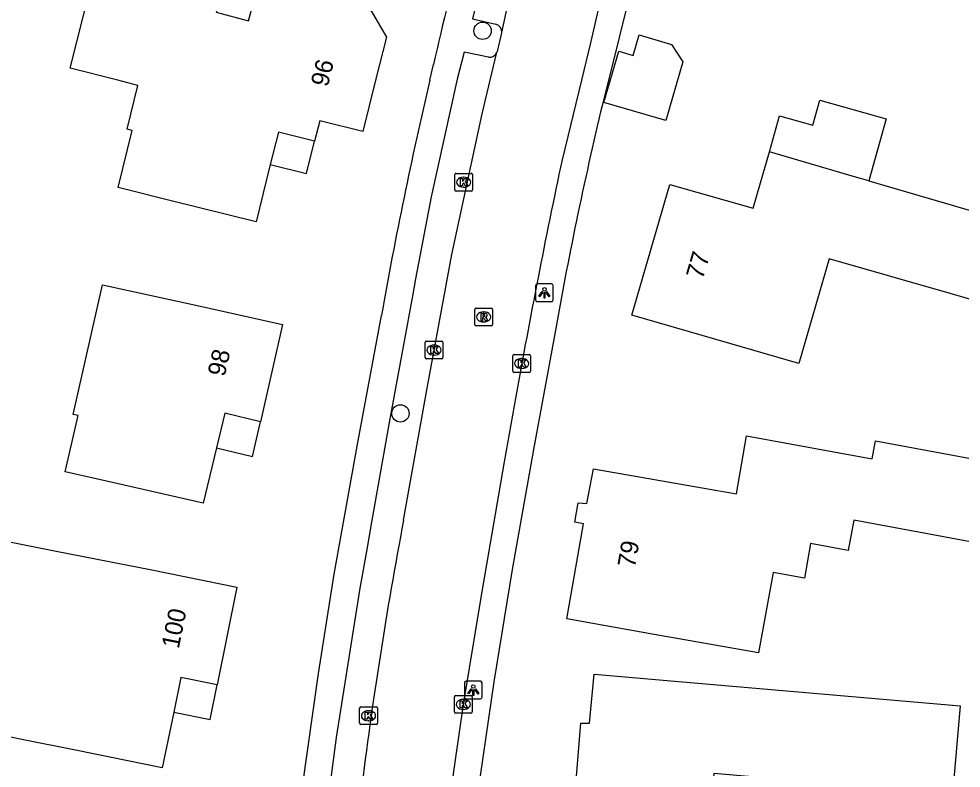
# Model space of a CAD drawing. Extents: x 157767 to 159171, y 387842 to 389425.
# Drawn here: x 158027.9 to 158081, y 388711.2 to 388753.5 of the extents above; entities that cross this region are included whole.
import ezdxf

# ---------------------------------------------------------------- set-up
doc = ezdxf.new("R2010")
doc.units = 0
for name, color, linetype in [('IMGEO_Boom', 7, 'Continuous'), ('IMGEO_Kolk', 7, 'Continuous'), ('IMGEO_Lichtpunt', 7, 'Continuous'), ('IMGEO_Pand', 7, 'Continuous'), ('IMGEO_Pand_nummerreeks', 7, 'Continuous'), ('IMGEO_Pand_overbouw', 7, 'Continuous'), ('IMGEO_Rijbaan_lokaal_open', 7, 'Continuous'), ('IMGEO_Rioolput', 7, 'Continuous'), ('IMGEO_Voetpad_open', 7, 'Continuous')]:
    doc.layers.add(name, color=color, linetype=linetype)

msp = doc.modelspace()

# ---------------------------------------------------------------- linework, layer by layer
at = {"layer": 'IMGEO_Boom'}
for centre in [(158054.035, 388752.789), (158049.41, 388731.223)]:
    msp.add_circle(centre, 0.489, dxfattribs=at)
at = {"layer": 'IMGEO_Kolk'}
for p, q in [((158052.469, 388743.83), (158052.469, 388744.682)), ((158052.544, 388744.756), (158053.396, 388744.756)), ((158053.47, 388744.682), (158053.47, 388743.83)), ((158052.957, 388744.536), (158052.982, 388744.536)), ((158053.396, 388743.756), (158052.544, 388743.756)), ((158052.98, 388743.976), (158052.955, 388743.976)), ((158050.803, 388734.369), (158050.803, 388735.221)), ((158050.878, 388735.295), (158051.73, 388735.295)), ((158051.804, 388735.221), (158051.804, 388734.369)), ((158051.291, 388735.075), (158051.316, 388735.075)), ((158051.73, 388734.295), (158050.878, 388734.295)), ((158051.314, 388734.515), (158051.289, 388734.515)), ((158055.742, 388733.611), (158055.742, 388734.463)), ((158055.817, 388734.537), (158056.669, 388734.537)), ((158056.23, 388734.317), (158056.255, 388734.317)), ((158056.743, 388734.463), (158056.743, 388733.611)), ((158056.669, 388733.537), (158055.817, 388733.537)), ((158056.253, 388733.757), (158056.228, 388733.757)), ((158052.448, 388714.397), (158052.448, 388715.249)), ((158052.523, 388715.323), (158053.375, 388715.323)), ((158052.936, 388715.103), (158052.961, 388715.103)), ((158053.449, 388715.249), (158053.449, 388714.397)), ((158047.109, 388713.756), (158047.109, 388714.608)), ((158047.184, 388714.682), (158048.036, 388714.682)), ((158047.597, 388714.462), (158047.622, 388714.462)), ((158048.11, 388714.608), (158048.11, 388713.756)), ((158052.959, 388714.543), (158052.934, 388714.543)), ((158047.62, 388713.902), (158047.595, 388713.902)), ((158053.375, 388714.323), (158052.523, 388714.323)), ((158048.036, 388713.682), (158047.184, 388713.682))]:
    msp.add_line(p, q, dxfattribs=at)
for points in [[(158052.469, 388743.83), (158052.469, 388744.682)], [(158052.544, 388744.756), (158053.396, 388744.756)], [(158053.47, 388744.682), (158053.47, 388743.83)], [(158052.79, 388744.456), (158052.913, 388744.456), (158052.913, 388744.305), (158053.043, 388744.456), (158053.207, 388744.456), (158053.061, 388744.305), (158053.214, 388744.056), (158053.062, 388744.056), (158052.977, 388744.22), (158052.913, 388744.153), (158052.913, 388744.056), (158052.79, 388744.056), (158052.79, 388744.456)], [(158053.396, 388743.756), (158052.544, 388743.756)], [(158050.803, 388734.369), (158050.803, 388735.221)], [(158050.878, 388735.295), (158051.73, 388735.295)], [(158051.804, 388735.221), (158051.804, 388734.369)], [(158051.124, 388734.995), (158051.247, 388734.995), (158051.247, 388734.844), (158051.377, 388734.995), (158051.541, 388734.995), (158051.395, 388734.844), (158051.548, 388734.595), (158051.396, 388734.595), (158051.311, 388734.759), (158051.247, 388734.692), (158051.247, 388734.595), (158051.124, 388734.595), (158051.124, 388734.995)], [(158051.73, 388734.295), (158050.878, 388734.295)], [(158055.742, 388733.611), (158055.742, 388734.463)], [(158055.817, 388734.537), (158056.669, 388734.537)], [(158056.063, 388734.237), (158056.186, 388734.237), (158056.186, 388734.086), (158056.316, 388734.237), (158056.48, 388734.237), (158056.334, 388734.086), (158056.487, 388733.837), (158056.335, 388733.837), (158056.25, 388734.001), (158056.186, 388733.934), (158056.186, 388733.837), (158056.063, 388733.837), (158056.063, 388734.237)], [(158056.743, 388734.463), (158056.743, 388733.611)], [(158056.669, 388733.537), (158055.817, 388733.537)], [(158052.448, 388714.397), (158052.448, 388715.249)], [(158052.523, 388715.323), (158053.375, 388715.323)], [(158052.769, 388715.023), (158052.892, 388715.023), (158052.892, 388714.872), (158053.022, 388715.023), (158053.186, 388715.023), (158053.04, 388714.872), (158053.193, 388714.623), (158053.041, 388714.623), (158052.956, 388714.787), (158052.892, 388714.72), (158052.892, 388714.623), (158052.769, 388714.623), (158052.769, 388715.023)], [(158053.449, 388715.249), (158053.449, 388714.397)], [(158047.109, 388713.756), (158047.109, 388714.608)], [(158047.184, 388714.682), (158048.036, 388714.682)], [(158048.11, 388714.608), (158048.11, 388713.756)], [(158047.43, 388714.382), (158047.553, 388714.382), (158047.553, 388714.231), (158047.683, 388714.382), (158047.847, 388714.382), (158047.701, 388714.231), (158047.854, 388713.982), (158047.702, 388713.982), (158047.617, 388714.146), (158047.553, 388714.079), (158047.553, 388713.982), (158047.43, 388713.982), (158047.43, 388714.382)], [(158053.375, 388714.323), (158052.523, 388714.323)], [(158048.036, 388713.682), (158047.184, 388713.682)]]:
    msp.add_lwpolyline(points, dxfattribs=at)
for centre, start, end in [((158052.546, 388744.68), 91.552, 178.448), ((158052.546, 388744.68), 91.552, 178.448), ((158053.394, 388744.68), 1.552, 88.448), ((158053.394, 388744.68), 1.552, 88.448), ((158052.546, 388743.832), 181.552, 268.448), ((158052.546, 388743.832), 181.552, 268.448), ((158053.394, 388743.832), 271.552, 358.448), ((158053.394, 388743.832), 271.552, 358.448), ((158050.88, 388735.219), 91.552, 178.448), ((158050.88, 388735.219), 91.552, 178.448), ((158051.728, 388735.219), 1.552, 88.448), ((158051.728, 388735.219), 1.552, 88.448), ((158050.88, 388734.371), 181.552, 268.448), ((158050.88, 388734.371), 181.552, 268.448), ((158051.728, 388734.371), 271.552, 358.448), ((158051.728, 388734.371), 271.552, 358.448), ((158055.819, 388734.461), 91.552, 178.448), ((158055.819, 388734.461), 91.552, 178.448), ((158056.667, 388734.461), 1.552, 88.448), ((158056.667, 388734.461), 1.552, 88.448), ((158055.819, 388733.613), 181.552, 268.448), ((158055.819, 388733.613), 181.552, 268.448), ((158056.667, 388733.613), 271.552, 358.448), ((158056.667, 388733.613), 271.552, 358.448), ((158052.525, 388715.247), 91.552, 178.448), ((158052.525, 388715.247), 91.552, 178.448), ((158053.373, 388715.247), 1.552, 88.448), ((158053.373, 388715.247), 1.552, 88.448), ((158047.186, 388714.606), 91.552, 178.448), ((158047.186, 388714.606), 91.552, 178.448), ((158048.034, 388714.606), 1.552, 88.448), ((158048.034, 388714.606), 1.552, 88.448), ((158052.525, 388714.399), 181.552, 268.448), ((158052.525, 388714.399), 181.552, 268.448), ((158053.373, 388714.399), 271.552, 358.448), ((158053.373, 388714.399), 271.552, 358.448), ((158047.186, 388713.758), 181.552, 268.448), ((158047.186, 388713.758), 181.552, 268.448), ((158048.034, 388713.758), 271.552, 358.448), ((158048.034, 388713.758), 271.552, 358.448)]:
    msp.add_arc(centre, 0.0765, start, end, dxfattribs=at)
for centre, major_axis, ratio, start_param, end_param in [((158052.956, 388744.256), (-0.387, 0.002), 0.722429, 4.712389, 7.853982), ((158052.981, 388744.256), (-0.39, 0.002), 0.717154, 1.570796, 4.712389), ((158051.29, 388734.795), (-0.387, 0.002), 0.722429, 4.712389, 7.853982), ((158051.315, 388734.795), (-0.39, 0.002), 0.717154, 1.570796, 4.712389), ((158056.229, 388734.037), (-0.387, 0.002), 0.722429, 4.712389, 7.853982), ((158056.254, 388734.037), (-0.39, 0.002), 0.717154, 1.570796, 4.712389), ((158052.935, 388714.823), (-0.387, 0.002), 0.722429, 4.712389, 7.853982), ((158052.96, 388714.823), (-0.39, 0.002), 0.717154, 1.570796, 4.712389), ((158047.596, 388714.182), (-0.387, 0.002), 0.722429, 4.712389, 7.853982), ((158047.621, 388714.182), (-0.39, 0.002), 0.717154, 1.570796, 4.712389)]:
    msp.add_ellipse(centre, major_axis=major_axis, ratio=ratio, start_param=start_param, end_param=end_param, dxfattribs=at)
at = {"layer": 'IMGEO_Lichtpunt'}
for p, q in [((158057.022, 388738.424), (158057.022, 388737.617)), ((158057.022, 388738.424), (158057.022, 388737.617)), ((158057.924, 388738.519), (158057.116, 388738.519)), ((158057.924, 388738.519), (158057.116, 388738.519)), ((158058.018, 388737.617), (158058.018, 388738.424)), ((158058.018, 388737.617), (158058.018, 388738.424)), ((158057.116, 388737.523), (158057.924, 388737.523)), ((158057.116, 388737.523), (158057.924, 388737.523)), ((158053.015, 388716.035), (158053.015, 388715.228)), ((158053.015, 388716.035), (158053.015, 388715.228)), ((158053.917, 388716.13), (158053.109, 388716.13)), ((158053.917, 388716.13), (158053.109, 388716.13)), ((158054.011, 388715.228), (158054.011, 388716.035)), ((158054.011, 388715.228), (158054.011, 388716.035)), ((158053.109, 388715.134), (158053.917, 388715.134)), ((158053.109, 388715.134), (158053.917, 388715.134))]:
    msp.add_line(p, q, dxfattribs=at)
for points in [[(158057.396, 388738.088), (158057.435, 388738.06), (158057.247, 388737.798), (158057.209, 388737.825), (158057.396, 388738.088)], [(158057.498, 388738.04), (158057.545, 388738.04), (158057.545, 388737.718), (158057.498, 388737.718), (158057.498, 388738.04)], [(158057.608, 388738.06), (158057.646, 388738.087), (158057.833, 388737.825), (158057.794, 388737.797), (158057.608, 388738.06)], [(158053.389, 388715.699), (158053.428, 388715.671), (158053.24, 388715.409), (158053.202, 388715.436), (158053.389, 388715.699)], [(158053.491, 388715.651), (158053.538, 388715.651), (158053.538, 388715.329), (158053.491, 388715.329), (158053.491, 388715.651)], [(158053.601, 388715.671), (158053.639, 388715.698), (158053.826, 388715.436), (158053.787, 388715.408), (158053.601, 388715.671)]]:
    msp.add_lwpolyline(points, dxfattribs=at)
for centre in [(158057.521, 388738.222), (158053.514, 388715.833)]:
    msp.add_circle(centre, 0.0994, dxfattribs=at)
for centre, start, end in [((158057.116, 388738.424), 90, 180), ((158057.116, 388738.424), 90, 180), ((158057.924, 388738.424), 0, 90), ((158057.924, 388738.424), 0, 90), ((158057.116, 388737.617), 180, 270), ((158057.116, 388737.617), 180, 270), ((158057.924, 388737.617), 270, 0), ((158057.924, 388737.617), 270, 360), ((158053.109, 388716.035), 90, 180), ((158053.109, 388716.035), 90, 180), ((158053.917, 388716.035), 0, 90), ((158053.917, 388716.035), 0, 90), ((158053.109, 388715.228), 180, 270), ((158053.109, 388715.228), 180, 270), ((158053.917, 388715.228), 270, 0), ((158053.917, 388715.228), 270, 360)]:
    msp.add_arc(centre, 0.0946, start, end, dxfattribs=at)
at = {"layer": 'IMGEO_Pand'}
for points in [[(158039.641, 388756.097), (158039.035, 388753.844), (158040.852, 388753.355), (158041.459, 388755.609), (158047.751, 388753.915), (158048.618, 388752.439), (158048.008, 388750), (158047.286, 388747.113), (158044.86, 388747.72), (158044.574, 388746.575), (158042.532, 388747.083), (158042.076, 388745.249), (158041.274, 388742.027), (158036.422, 388743.233), (158033.501, 388743.959), (158034.298, 388747.166), (158034.007, 388747.238), (158034.623, 388749.716), (158033.49, 388750), (158030.796, 388750.675), (158032.65, 388757.979), (158034.813, 388757.397), (158039.641, 388756.097)], [(158064.351, 388747.739), (158060.872, 388748.748), (158061.71, 388751.639), (158062.516, 388751.405), (158062.85, 388752.554), (158064.681, 388752.023), (158065.312, 388751.05), (158064.351, 388747.739)], [(158070.191, 388745.965), (158070.768, 388747.997), (158072.64, 388747.466), (158073.044, 388748.889), (158076.781, 388747.828), (158075.789, 388744.331)], [(158075.789, 388744.331), (158081.72, 388742.6), (158085.94, 388741.382), (158084.606, 388736.762), (158080.38, 388737.98), (158073.565, 388739.944), (158071.86, 388734.03), (158067.254, 388735.368), (158062.452, 388736.763), (158064.588, 388744.125), (158069.289, 388742.786), (158070.191, 388745.965)], [(158075.789, 388744.331), (158074.991, 388744.564), (158070.191, 388745.965)], [(158042.77, 388736.244), (158041.518, 388730.754), (158039.511, 388731.234), (158039.045, 388729.289), (158038.297, 388726.167), (158033.422, 388727.276), (158030.525, 388727.935), (158031.256, 388731.104), (158030.963, 388731.17), (158032.616, 388738.481), (158037.888, 388737.32), (158042.77, 388736.244)], [(158084.862, 388723.375), (158074.95, 388725.205), (158074.636, 388723.504), (158072.511, 388723.897), (158072.164, 388721.947), (158070.4, 388722.259), (158069.578, 388717.73), (158063.701, 388718.771), (158058.777, 388719.644), (158059.718, 388725.009), (158059.233, 388725.097), (158059.43, 388726.184), (158059.91, 388726.139), (158060.281, 388728.104), (158064.478, 388727.37), (158068.338, 388726.695), (158068.912, 388729.966), (158073.83, 388729.06), (158075.984, 388728.664), (158076.171, 388729.677), (158085.7, 388727.918), (158084.862, 388723.375)], [(158035.301, 388722.419), (158040.2, 388721.432), (158039.082, 388715.925), (158037.037, 388716.343), (158036.636, 388714.383), (158035.992, 388711.238), (158031.093, 388712.236), (158028.164, 388712.832), (158022.68, 388713.949), (158024.826, 388724.486), (158030.007, 388723.457), (158035.301, 388722.419)], [(158080.501, 388709.757), (158067.071, 388710.925), (158066.22, 388701.144), (158066.044, 388701.143), (158055.811, 388701.08), (158055.805, 388701.309), (158061.048, 388701.364), (158061.329, 388705.093), (158058.892, 388705.298), (158059.02, 388707.115), (158059.638, 388707.113), (158059.76, 388708.602), (158059.153, 388708.699), (158059.578, 388713.774), (158060.055, 388713.766), (158060.317, 388716.531), (158065.299, 388716.099), (158080.941, 388714.743), (158080.501, 388709.757)]]:
    msp.add_lwpolyline(points, dxfattribs=at)
at = {"layer": 'IMGEO_Pand_overbouw'}
for points in [[(158042.076, 388745.249), (158044.116, 388744.742), (158044.574, 388746.575), (158042.532, 388747.083)], [(158041.518, 388730.754), (158039.511, 388731.234), (158039.045, 388729.289), (158041.073, 388728.803)], [(158036.636, 388714.383), (158038.684, 388713.964), (158039.082, 388715.925), (158037.037, 388716.343)]]:
    msp.add_lwpolyline(points, close=True, dxfattribs=at)
at = {"layer": 'IMGEO_Rijbaan_lokaal_open'}
for points in [[(158055.112, 388752.7), (158055.71, 388755.405), (158057.732, 388763.261), (158059.448, 388769.818), (158060.899, 388775.062), (158061.414, 388776.868)], [(158062.36, 388761.143), (158060.611, 388754.226), (158060.123, 388752.119), (158059.606, 388750), (158058.514, 388745.523)], [(158055.112, 388752.7), (158055.108, 388752.668), (158054.849, 388751.617), (158054.837, 388751.587)], [(158049.585, 388725.204), (158050.91, 388732.647), (158052.303, 388740.19), (158054.01, 388748.11), (158054.837, 388751.587)], [(158055.911, 388732.171), (158055.255, 388728.503), (158053.952, 388720.966), (158052.948, 388714.823), (158052.465, 388711.558), (158051.695, 388706.09), (158051.095, 388701.609), (158050.612, 388697.963), (158050.2, 388694.406), (158049.727, 388690.157)]]:
    msp.add_lwpolyline(points, dxfattribs=at)
for centre, radius, start, end in [((158474.348, 388657.526), 425.043, 168.05153, 169.88534), ((158285.1, 388680.505), 239.719, 169.25361, 172.97781)]:
    msp.add_arc(centre, radius, start, end, dxfattribs=at)
at = {"layer": 'IMGEO_Rioolput'}
for p, q in [((158053.597, 388736.236), (158053.597, 388737.088)), ((158053.672, 388737.162), (158054.524, 388737.162)), ((158054.085, 388736.942), (158054.11, 388736.942)), ((158054.598, 388737.088), (158054.598, 388736.236)), ((158054.108, 388736.382), (158054.083, 388736.382)), ((158054.524, 388736.162), (158053.672, 388736.162))]:
    msp.add_line(p, q, dxfattribs=at)
for points in [[(158053.597, 388736.236), (158053.597, 388737.088)], [(158053.672, 388737.162), (158054.524, 388737.162)], [(158054.186, 388736.86), (158053.934, 388736.862), (158053.934, 388736.462)], [(158054.112, 388736.781), (158054.058, 388736.781), (158054.058, 388736.7)], [(158054.598, 388737.088), (158054.598, 388736.236)], [(158053.934, 388736.462), (158054.058, 388736.462), (158054.058, 388736.624), (158054.069, 388736.624)], [(158054.058, 388736.7), (158054.11, 388736.7)], [(158054.116, 388736.595), (158054.187, 388736.462), (158054.327, 388736.462), (158054.262, 388736.588)], [(158054.524, 388736.162), (158053.672, 388736.162)]]:
    msp.add_lwpolyline(points, dxfattribs=at)
for centre, radius, start, end in [((158053.674, 388737.086), 0.0765, 91.552, 178.448), ((158053.674, 388737.086), 0.0765, 91.552, 178.448), ((158054.118, 388736.685), 0.0964, 77.0061, 93.1865), ((158054.132, 388736.742), 0.0378, 276.6634, 79.6772), ((158054.185, 388736.75), 0.109, 350.3612, 89.416), ((158054.183, 388736.75), 0.112, 277.5842, 350.9817), ((158054.522, 388737.086), 0.0765, 1.552, 88.448), ((158054.522, 388737.086), 0.0765, 1.552, 88.448), ((158053.674, 388736.238), 0.0765, 181.552, 268.448), ((158053.674, 388736.238), 0.0765, 181.552, 268.448), ((158054.068, 388736.571), 0.0533, 26.0293, 88.6989), ((158054.094, 388736.889), 0.19, 274.7715, 282.9687), ((158054.167, 388736.535), 0.108, 29.5134, 73.7905), ((158054.522, 388736.238), 0.0765, 271.552, 358.448), ((158054.522, 388736.238), 0.0765, 271.552, 358.448)]:
    msp.add_arc(centre, radius, start, end, dxfattribs=at)
for centre, major_axis, ratio, start_param, end_param in [((158054.084, 388736.662), (-0.387, 0.002), 0.722429, 4.712389, 7.853982), ((158054.109, 388736.662), (-0.39, 0.002), 0.717154, 1.570796, 4.712389)]:
    msp.add_ellipse(centre, major_axis=major_axis, ratio=ratio, start_param=start_param, end_param=end_param, dxfattribs=at)
at = {"layer": 'IMGEO_Voetpad_open'}
for points in [[(158060.928, 388776.565), (158059.585, 388776.921), (158058.564, 388773.111), (158057.252, 388768.334), (158057.069, 388767.668), (158056.28, 388764.708), (158053.66, 388754.232), (158053.461, 388753.463), (158054.787, 388753.164)], [(158064.4, 388763.047), (158063.616, 388759.985), (158060.784, 388748.63)], [(158054.362, 388751.3), (158053.002, 388751.59), (158052.609, 388750.061), (158051.141, 388743.431), (158050.419, 388739.693), (158050.262, 388738.818), (158050.108, 388737.945), (158048.766, 388730.705), (158047.777, 388725.09), (158047.507, 388723.557), (158047.113, 388721.37), (158045.789, 388712.963), (158045.298, 388709.238), (158044.841, 388705.729), (158043.814, 388698.007), (158043.503, 388695.577), (158043.348, 388694.27)], [(158051.06, 388750), (158051.269, 388750.886)], [(158041.406, 388689.153), (158041.767, 388693.388), (158042.265, 388697.737), (158042.741, 388701.651), (158043.331, 388705.99), (158043.884, 388710.198), (158044.788, 388716.563), (158045.681, 388722.155), (158046.965, 388729.378), (158048.336, 388736.749)], [(158058.065, 388735.51), (158056.909, 388729.188), (158055.696, 388722.426), (158054.662, 388716.097), (158053.604, 388708.729), (158052.421, 388700.293), (158051.744, 388694.37), (158051.149, 388689.122)]]:
    msp.add_lwpolyline(points, dxfattribs=at)
for centre, radius, start, end in [((158486.643, 388650.337), 446.834, 165.13061, 166.99563), ((158054.673, 388752.738), 0.441, 354.9981, 75.0191), ((158054.394, 388751.784), 0.485, 266.2459, 336.0357), ((158298.841, 388692.158), 254.443, 166.86025, 169.90688), ((158278.002, 388696.772), 223.323, 166.57266, 170.01077)]:
    msp.add_arc(centre, radius, start, end, dxfattribs=at)

# ---------------------------------------------------------------- texts
at = {"layer": 'IMGEO_Pand_nummerreeks'}
for s, rotation, p in [('96', 75.9587, (158045.309, 388749.587)), ('77', 73.8199, (158066.439, 388738.736)), ('98', 77.1533, (158039.505, 388733.257)), ('79', 79.9194, (158062.613, 388722.486)), ('100', 78.5239, (158036.917, 388717.922))]:
    msp.add_text(s, height=1, rotation=rotation, dxfattribs=at).set_placement(p)

doc.saveas('drawing.dxf')
